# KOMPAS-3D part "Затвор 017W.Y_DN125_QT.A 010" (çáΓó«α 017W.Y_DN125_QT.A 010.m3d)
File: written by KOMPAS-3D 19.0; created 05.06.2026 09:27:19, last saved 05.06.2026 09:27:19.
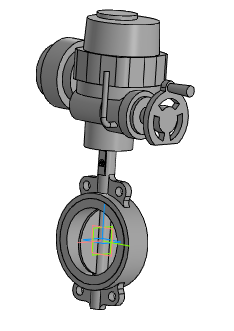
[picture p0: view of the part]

Document properties: Автор: Энергия; Полное имя файла: ..\..\..\3d для проектировщиков\x.x Тип 017W.Y(S) Затвор дисковый поворотный межфланцевый\Затвор 017W.Y(S)_DN32-DN1200_QT.A_MT903.A\Затвор 017W.Y_DN125_QT.A 010.a3d

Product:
- Part/product: Затвор 017W.Y_DN125_QT.A 010
    Масса: 43.8882

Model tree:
1. Операция без истории:1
